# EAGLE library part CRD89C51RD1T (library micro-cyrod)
8 bit, fast, microcontroller with 64KB program/ISP Flash and 2KB RAM Auto generated by make-symbol-device-package-bsdl.ulp Rev. 34 Source: www.cyrod.com .. CRD89C51RD1T-V10.pdf
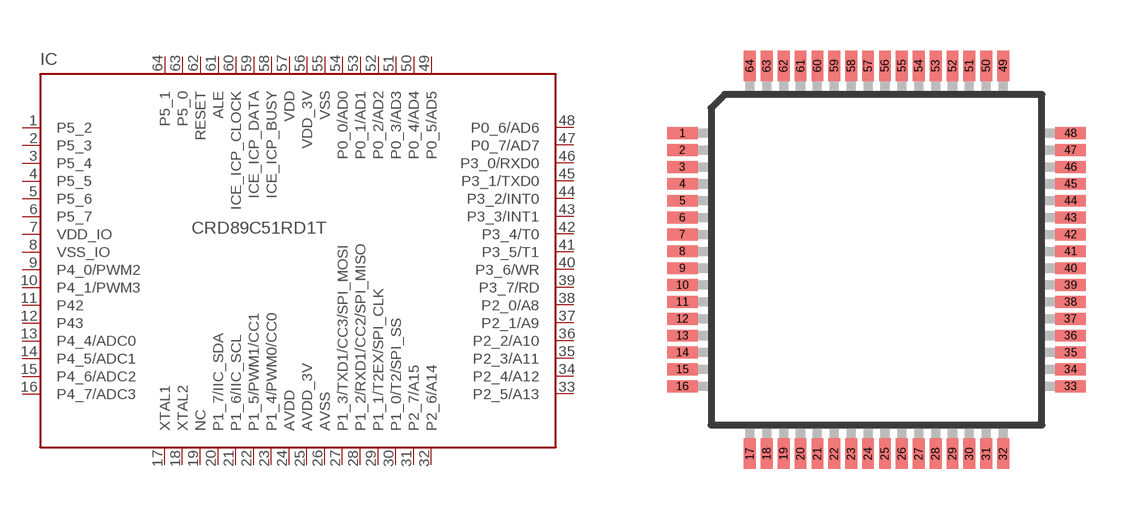
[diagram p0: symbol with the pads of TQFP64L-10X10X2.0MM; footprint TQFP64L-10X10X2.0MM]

Designator prefix IC

## CRD89C51RD1T (OC_FARNELL: unknown; OC_NEWARK: unknown)  [TQFP64L-10X10X2.0MM]
1  P5_2
2  P5_3
3  P5_4
4  P5_5
5  P5_6
6  P5_7
7  VDD_IO  pwr
8  VSS_IO  pwr
9  P4_0/PWM2
10  P4_1/PWM3
11  P42
12  P43
13  P4_4/ADC0
14  P4_5/ADC1
15  P4_6/ADC2
16  P4_7/ADC3
17  XTAL1  in
18  XTAL2  out
19  NC  nc
20  P1_7/IIC_SDA
21  P1_6/IIC_SCL
22  P1_5/PWM1/CC1
23  P1_4/PWM0/CC0
24  AVDD  pwr
25  AVDD_3V  pwr
26  AVSS  pwr
27  P1_3/TXD1/CC3/SPI_MOSI
28  P1_2/RXD1/CC2/SPI_MISO
29  P1_1/T2EX/SPI_CLK
30  P1_0/T2/SPI_SS
31  P2_7/A15
32  P2_6/A14
33  P2_5/A13
34  P2_4/A12
35  P2_3/A11
36  P2_2/A10
37  P2_1/A9
38  P2_0/A8
39  P3_7/RD
40  P3_6/WR
41  P3_5/T1
42  P3_4/T0
43  P3_3/INT1
44  P3_2/INT0
45  P3_1/TXD0
46  P3_0/RXD0
47  P0_7/AD7
48  P0_6/AD6
49  P0_5/AD5
50  P0_4/AD4
51  P0_3/AD3
52  P0_2/AD2
53  P0_1/AD1
54  P0_0/AD0
55  VSS  pwr
56  VDD_3V  pwr
57  VDD  pwr
58  ICE_ICP_BUSY  out
59  ICE_ICP_DATA
60  ICE_ICP_CLOCK
61  ALE  out
62  RESET  in
63  P5_0
64  P5_1

## Footprint TQFP64L-10X10X2.0MM (pad centres in mm)
TQFP 64L-10X10X2.0 MM Auto generated by make-symbol-device-package-bsdl.ulp Rev. 34 Source: www.cyrod.com .. CRD89C51RD1T-V10.pdf
smd 0.9 x 0.35: 1 -5.75,3.75; 2 -5.75,3.25; 3 -5.75,2.75; 4 -5.75,2.25; 5 -5.75,1.75; 6 -5.75,1.25; 7 -5.75,0.75; 8 -5.75,0.25; 9 -5.75,-0.25; 10 -5.75,-0.75; 11 -5.75,-1.25; 12 -5.75,-1.75; 13 -5.75,-2.25; 14 -5.75,-2.75; 15 -5.75,-3.25; 16 -5.75,-3.75; 33 5.75,-3.75; 34 5.75,-3.25; 35 5.75,-2.75; 36 5.75,-2.25; 37 5.75,-1.75; 38 5.75,-1.25; 39 5.75,-0.75; 40 5.75,-0.25; 41 5.75,0.25; 42 5.75,0.75; 43 5.75,1.25; 44 5.75,1.75; 45 5.75,2.25; 46 5.75,2.75; 47 5.75,3.25; 48 5.75,3.75
smd 0.35 x 0.9: 17 -3.75,-5.75; 18 -3.25,-5.75; 19 -2.75,-5.75; 20 -2.25,-5.75; 21 -1.75,-5.75; 22 -1.25,-5.75; 23 -0.75,-5.75; 24 -0.25,-5.75; 25 0.25,-5.75; 26 0.75,-5.75; 27 1.25,-5.75; 28 1.75,-5.75; 29 2.25,-5.75; 30 2.75,-5.75; 31 3.25,-5.75; 32 3.75,-5.75; 49 3.75,5.75; 50 3.25,5.75; 51 2.75,5.75; 52 2.25,5.75; 53 1.75,5.75; 54 1.25,5.75; 55 0.75,5.75; 56 0.25,5.75; 57 -0.25,5.75; 58 -0.75,5.75; 59 -1.25,5.75; 60 -1.75,5.75; 61 -2.25,5.75; 62 -2.75,5.75; 63 -3.25,5.75; 64 -3.75,5.75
